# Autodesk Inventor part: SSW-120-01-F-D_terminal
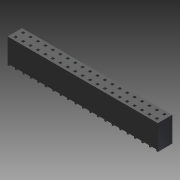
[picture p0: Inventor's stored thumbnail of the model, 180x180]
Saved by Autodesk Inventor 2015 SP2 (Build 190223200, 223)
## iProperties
Category: PARTsolutions
Company: SAMTEC
Created: 2015-08
Part Number: SSW-120-01-F-D_terminal
Catalog Web Link: www.cadenas.de
Description: SSW Series Terminal-SSW Series - (2,54 mm) .100" Surface Mount Terminal & Through-Hole .025" Square Post Socket
Vendor: SAMTEC
Document SubType Name: Modeling
Designer: PARTuser1
Manufacturer: SAMTEC
Mass: 1.8617 g
Surface Area: 24.8346 cm^2
Volume: 1.8617 cm^3
Density: 1 g/cm^3
Material: Allgemein
Appearance: PSOLRGB-175-175-175
PSOL_IDENT_0: {$CADENAS_DATA\23d-libs\samtec\modelling\ssw\parts\ssw_terminal.prj},256 {VTYP=3D},{NB=SSW-120-01-F-
PSOL_IDENT_1: D_terminal},{LINA=SSW-120-01-F-D_terminal},{NN=SSW Series Terminal},{DATE=20.05.2015 07:57:00},{GEOM
PSOL_IDENT_2: DATE=20.05.2015 07:56:00},{VERSION=},{LINEID=10},{LINESUBID=-1},{WBVAR=POS,LS,PLOPT,ROW,TOPT,POLOPT,
PSOL_IDENT_3: NOPT,LLOPT,POPT,KOPT,TROPT}  {NB=SSW-120-01-F-D_terminal},{LINA=SSW-120-01-F-D_terminal},{KT=DUMMY},
PSOL_IDENT_4: {PN=SSW-120-01-F-D},{SERIES=SSW},{POS=20},{POSATOF=20},{LS=01},{LSALG= '01','-01','02','-02','03','-
PSOL_IDENT_5: 03','04','-04','06','-06','21','-21','22','-22','23','-23','24','-24' },{PLOPT=F},{PLOPTALG= 'G','-G
PSOL_IDENT_6: - Gold, 20micro\" Au / 50micro\" Ni Min on Contact, 3micro\" Au / 50micro\" Ni Min on Tail','S','-S
PSOL_IDENT_7: - Selective, 30micro\" Au / 50micro\" Ni Min on Contact, Matte Tin Tail','H','-H - Heavy Gold 30mic
PSOL_IDENT_8: ro\" Au / 50micro\" Ni Min on Contact, 3micro\" Au / 50micro\" Ni Min on Tail' ,'F','-F - Flash Sele
PSOL_IDENT_9: ctive, 3micro\" Au / 50micro\" Ni Min on Contact, Matte Tin Tail','STL','-STL - Selective, 30micro\"
PSOL_IDENT_10: Au / 50micro\" Ni Min on Contact Area, Tin/Lead (90/10 +/-5%) Tail','SM','-SM - Selective, 30micro\
PSOL_IDENT_11: " Au / 50micro\" Ni Min on Contact, Matte Tin Tail','FM','-FM - Flash Selective, 3micro\" Au / 50mic
PSOL_IDENT_12: ro\" Ni Min on Contact, Matte Tin Tail','L','-L - Light Selective, 10micro\" Au / 50micro\" Ni Min o
PSOL_IDENT_13: n Contact Area, Matte Tin Tail','T','-T - Matte Tin Contact and Tail','E','-E - 50micro\" Extra Heav
PSOL_IDENT_14: y Gold in Contact Area, 3micro\" Gold on Tail','TL','-TL - Tin/Lead (90/10 ± 5%) Contact and Tail','
PSOL_IDENT_15: TM','-TM - Matte Tin Contact and Tail' },{ROW=D},{ROWALG= 'S','-S - Single','D','-D - Double','T','-
PSOL_IDENT_16: T - Triple', 'P','-P - Single Notched','Q','-Q - Triple with only Outer 2 Rows Filled' },{TOPT=},{TO
PSOL_IDENT_17: PTALG= '','Straight' },{TOPTPN=},{POLOPT=},{POLOPTALG= '','Not Selected','001','001','002','002','00
PSOL_IDENT_18: 3','003','004','004','005','005','006','006','007','007','008','008','009','009','010','010','011','
PSOL_IDENT_19: 011','012','012','013','013','014','014','015','015','016','016','017','017','018','018','019','019'
PSOL_IDENT_20: ,'020','020','021','021','022','022','023','023','024','024','025','025','026','026','027','027','02
PSOL_IDENT_21: 8','028','029','029','030','030','031','031','032','032','033','033','034','034','035','035','036','
PSOL_IDENT_22: 036','037','037','038','038','039','039','040','040' },{POLOPTMAX=480},{POLOPTMAX2='001','001','002'
PSOL_IDENT_23: ,'002','003','003','004','004','005','005','006','006','007','007','008','008','009','009','010','01
PSOL_IDENT_24: 0','011','011','012','012','013','013','014','014','015','015','016','016','017','017','018','018','
PSOL_IDENT_25: 019','019','020','020','021','021','022','022','023','023','024','024','025','025','026','026','027'
PSOL_IDENT_26: ,'027','028','028','029','029','030','030','031','031','032','032','033','033','034','034','035','03
PSOL_IDENT_27: 5','036','036','037','037','038','038','039','039','040','040'},{POLARIZE='001','001','002','002','0
PSOL_IDENT_28: 03','003','004','004','005','005','006','006','007','007','008','008','009','009','010','010','011','
PSOL_IDENT_29: 011','012','012','013','013','014','014','015','015','016','016','017','017','018','018','019','019'
PSOL_IDENT_30: ,'020','020','021','021','022','022','023','023','024','024','025','025','026','026','027','027','02
PSOL_IDENT_31: 8','028','029','029','030','030','031','031','032','032','033','033','034','034','035','035','036','
PSOL_IDENT_32: 036','037','037','038','038','039','039','040','040','041','041','042','042','043','043','044','044'
PSOL_IDENT_33: ,'045','045','046','046','047','047','048','048','049','049','050','050','051','051','052','052','05
PSOL_IDENT_34: 3','053','054','054','055','055','056','056','057','057','058','058','059','059','060','060','061','
PSOL_IDENT_35: 061','062','062','063','063','064','064','065','065','066','066','067','067','068','068','069','069'
PSOL_IDENT_36: ,'070','070','071','071','072','072','073','073','074','074','075','075','076','076','077','077','07
PSOL_IDENT_37: 8','078','079','079','080','080','081','081','082','082','083','083','084','084','085','085','086','
PSOL_IDENT_38: 086','087','087','088','088','089','089','090','090','091','091','092','092','093','093','094','094'
PSOL_IDENT_39: ,'095','095','096','096','097','097','098','098','099','099','100','100','101','101','102','102','10
PSOL_IDENT_40: 3','103','104','104','105','105','106','106','107','107','108','108','109','109','110','110','111','
PSOL_IDENT_41: 111','112','112','113','113','114','114','115','115','116','116','117','117','118','118','119','119'
PSOL_IDENT_42: ,'120','120','121','121','122','122','123','123','124','124','125','125','126','126','127','127','12
PSOL_IDENT_43: 8','128','129','129','130','130','131','131','132','132','133','133','134','134','135','135','136','
PSOL_IDENT_44: 136','137','137','138','138','139','139','140','140','141','141','142','142','143','143','144','144'
PSOL_IDENT_45: ,'145','145','146','146','147','147','148','148','149','149','150','150'},{POLOPTPN=},{NOPT=},{NOPTA
PSOL_IDENT_46: LG= '','Not Selected','N','-N - Notch' },{NOPTPN=},{LLOPT=},{LLOPTALG= '','Not Selected','LL','-LL -
PSOL_IDENT_47: Locking Lead' },{LLOPTPN=},{POPT=},{POPTALG= '','Not Available' },{POPTPN=},{KOPT=},{KOPTALG= '','N
PSOL_IDENT_48: ot Available' },{KOPTPN=},{TROPT=},{TROPTALG= '','Not Available' },{TROPTPN=},{B=0.104},{C=0.000},{R=
PSOL_IDENT_49: 2.020},{APOPT=0.81250},{CPOPT=0.89750},{SKOPT=0.88200},{OEN=2},{POSX=1.01500},{POSY=0.01500},{POLOPT
PSOL_IDENT_50: ATOF=0},{POLMOVE=2}
NN: SSW Series Terminal
NT: SSW Series - (2,54 mm) .100" Surface Mount Terminal & Through-Hole .025" Square Post Socket
NB: SSW-120-01-F-D_terminal
NBSYN: $PN._terminal
LINA: SSW-120-01-F-D_terminal
SERIES: SSW
POS: -20
LS: -01
PLOPT: -F - Flash Selective, 3micro" Au / 50micro" Ni Min on Contact, Matte Tin Tail
ROW: -D - Double
TOPT: Straight
POLOPT: Not Selected
NOPT: Not Selected
LLOPT: Not Selected
POPT: Not Available
KOPT: Not Available
TROPT: Not Available
SUPPLIER: SAMTEC
ARTICLENO: SSW-120-01-F-D_terminal
BOMINFO: SSW-120-01-F-D_terminal
CREATOR: CADENAS GmbH
Title: SSW-120-01-F-D_terminal
Author: Cadenas PARTsolutions
Comments: SSW Series - (2,54 mm) .100" Surface Mount Terminal & Through-Hole .025" Square Post Socket
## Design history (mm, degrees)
sketch "Sketch_1"
  geometry: L1 (25.654, -2.477)-(25.654, 2.477); L2 (25.654, 2.477)-(-25.654, 2.477); L3 (-25.654, 2.477)-(-25.654, -2.477); L4 (-25.654, -2.477)-(25.654, -2.477); L5 (-23.736, 0.876)-(-23.736, 1.664); L6 (-23.736, 1.664)-(-24.524, 1.664); L7 (-24.524, 1.664)-(-24.524, 0.876); L8 (-24.524, 0.876)-(-23.736, 0.876); L9 (-23.736, -1.664)-(-23.736, -0.876); L10 (-23.736, -0.876)-(-24.524, -0.876); L11 (-24.524, -0.876)-(-24.524, -1.664); L12 (-24.524, -1.664)-(-23.736, -1.664); L13 (-21.196, 0.876)-(-21.196, 1.664); L14 (-21.196, 1.664)-(-21.984, 1.664); L15 (-21.984, 1.664)-(-21.984, 0.876); L16 (-21.984, 0.876)-(-21.196, 0.876); L17 (-21.196, -1.664)-(-21.196, -0.876); L18 (-21.196, -0.876)-(-21.984, -0.876); L19 (-21.984, -0.876)-(-21.984, -1.664); L20 (-21.984, -1.664)-(-21.196, -1.664); L21 (-18.656, 0.876)-(-18.656, 1.664); L22 (-18.656, 1.664)-(-19.444, 1.664); L23 (-19.444, 1.664)-(-19.444, 0.876); L24 (-19.444, 0.876)-(-18.656, 0.876); L25 (-18.656, -1.664)-(-18.656, -0.876); L26 (-18.656, -0.876)-(-19.444, -0.876); L27 (-19.444, -0.876)-(-19.444, -1.664); L28 (-19.444, -1.664)-(-18.656, -1.664); L29 (-16.116, 0.876)-(-16.116, 1.664); L30 (-16.116, 1.664)-(-16.904, 1.664); L31 (-16.904, 1.664)-(-16.904, 0.876); L32 (-16.904, 0.876)-(-16.116, 0.876); L33 (-16.116, -1.664)-(-16.116, -0.876); L34 (-16.116, -0.876)-(-16.904, -0.876); L35 (-16.904, -0.876)-(-16.904, -1.664); L36 (-16.904, -1.664)-(-16.116, -1.664); L37 (-13.576, 0.876)-(-13.576, 1.664); L38 (-13.576, 1.664)-(-14.364, 1.664); L39 (-14.364, 1.664)-(-14.364, 0.876); L40 (-14.364, 0.876)-(-13.576, 0.876); L41 (-13.576, -1.664)-(-13.576, -0.876); L42 (-13.576, -0.876)-(-14.364, -0.876); L43 (-14.364, -0.876)-(-14.364, -1.664); L44 (-14.364, -1.664)-(-13.576, -1.664); L45 (-11.036, 0.876)-(-11.036, 1.664); L46 (-11.036, 1.664)-(-11.824, 1.664); L47 (-11.824, 1.664)-(-11.824, 0.876); L48 (-11.824, 0.876)-(-11.036, 0.876); L49 (-11.036, -1.664)-(-11.036, -0.876); L50 (-11.036, -0.876)-(-11.824, -0.876); L51 (-11.824, -0.876)-(-11.824, -1.664); L52 (-11.824, -1.664)-(-11.036, -1.664); L53 (-8.496, 0.876)-(-8.496, 1.664); L54 (-8.496, 1.664)-(-9.284, 1.664); L55 (-9.284, 1.664)-(-9.284, 0.876); L56 (-9.284, 0.876)-(-8.496, 0.876); L57 (-8.496, -1.664)-(-8.496, -0.876); L58 (-8.496, -0.876)-(-9.284, -0.876); L59 (-9.284, -0.876)-(-9.284, -1.664); L60 (-9.284, -1.664)-(-8.496, -1.664); L61 (-5.956, 0.876)-(-5.956, 1.664); L62 (-5.956, 1.664)-(-6.744, 1.664); L63 (-6.744, 1.664)-(-6.744, 0.876); L64 (-6.744, 0.876)-(-5.956, 0.876)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
  constraints: 328 end point
extrude "Extrusion1" join sketch "Sketch_1" distance "d0" = 8.509; taper "d1" = 0 deg
sketch "Sketch_6"
  geometry: L1 (-25.146, -2.032)-(25.146, -2.032); L2 (25.146, -2.032)-(25.146, 0.508); L3 (25.146, 0.508)-(23.114, 0.508); L4 (23.114, 0.508)-(23.114, -1.27); L5 (23.114, -1.27)-(22.606, -1.27); L6 (22.606, -1.27)-(22.606, 0.508); L7 (22.606, 0.508)-(20.574, 0.508); L8 (20.574, 0.508)-(20.574, -1.27); L9 (20.574, -1.27)-(20.066, -1.27); L10 (20.066, -1.27)-(20.066, 0.508); L11 (20.066, 0.508)-(18.034, 0.508); L12 (18.034, 0.508)-(18.034, -1.27); L13 (18.034, -1.27)-(17.526, -1.27); L14 (17.526, -1.27)-(17.526, 0.508); L15 (17.526, 0.508)-(15.494, 0.508); L16 (15.494, 0.508)-(15.494, -1.27); L17 (15.494, -1.27)-(14.986, -1.27); L18 (14.986, -1.27)-(14.986, 0.508); L19 (14.986, 0.508)-(12.954, 0.508); L20 (12.954, 0.508)-(12.954, -1.27); L21 (12.954, -1.27)-(12.446, -1.27); L22 (12.446, -1.27)-(12.446, 0.508); L23 (12.446, 0.508)-(10.414, 0.508); L24 (10.414, 0.508)-(10.414, -1.27); L25 (10.414, -1.27)-(9.906, -1.27); L26 (9.906, -1.27)-(9.906, 0.508); L27 (9.906, 0.508)-(7.874, 0.508); L28 (7.874, 0.508)-(7.874, -1.27); L29 (7.874, -1.27)-(7.366, -1.27); L30 (7.366, -1.27)-(7.366, 0.508); L31 (7.366, 0.508)-(5.334, 0.508); L32 (5.334, 0.508)-(5.334, -1.27); L33 (5.334, -1.27)-(4.826, -1.27); L34 (4.826, -1.27)-(4.826, 0.508); L35 (4.826, 0.508)-(2.794, 0.508); L36 (2.794, 0.508)-(2.794, -1.27); L37 (2.794, -1.27)-(2.286, -1.27); L38 (2.286, -1.27)-(2.286, 0.508); L39 (2.286, 0.508)-(0.254, 0.508); L40 (0.254, 0.508)-(0.254, -1.27); L41 (0.254, -1.27)-(-0.254, -1.27); L42 (-0.254, -1.27)-(-0.254, 0.508); L43 (-0.254, 0.508)-(-2.286, 0.508); L44 (-2.286, 0.508)-(-2.286, -1.27); L45 (-2.286, -1.27)-(-2.794, -1.27); L46 (-2.794, -1.27)-(-2.794, 0.508); L47 (-2.794, 0.508)-(-4.826, 0.508); L48 (-4.826, 0.508)-(-4.826, -1.27); L49 (-4.826, -1.27)-(-5.334, -1.27); L50 (-5.334, -1.27)-(-5.334, 0.508); L51 (-5.334, 0.508)-(-7.366, 0.508); L52 (-7.366, 0.508)-(-7.366, -1.27); L53 (-7.366, -1.27)-(-7.874, -1.27); L54 (-7.874, -1.27)-(-7.874, 0.508); L55 (-7.874, 0.508)-(-9.906, 0.508); L56 (-9.906, 0.508)-(-9.906, -1.27); L57 (-9.906, -1.27)-(-10.414, -1.27); L58 (-10.414, -1.27)-(-10.414, 0.508); L59 (-10.414, 0.508)-(-12.446, 0.508); L60 (-12.446, 0.508)-(-12.446, -1.27); L61 (-12.446, -1.27)-(-12.954, -1.27); L62 (-12.954, -1.27)-(-12.954, 0.508); L63 (-12.954, 0.508)-(-14.986, 0.508); L64 (-14.986, 0.508)-(-14.986, -1.27)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
  constraints: 160 end point
extrude "Extrusion2" cut sketch "Sketch_6" stored distance "d2" = 10.16; taper "d3" = 0 deg
node "pin_XY"
node "pin_YZ"
node "pin_ZX"
node "pin_X"
node "pin_Y"
node "pin_Z"
node "pin_Center"
node "terminal_XY"
node "terminal_YZ"
node "terminal_ZX"
node "terminal_X"
node "terminal_Y"
node "terminal_Z"
node "terminal_Center"
body "Solid1"
